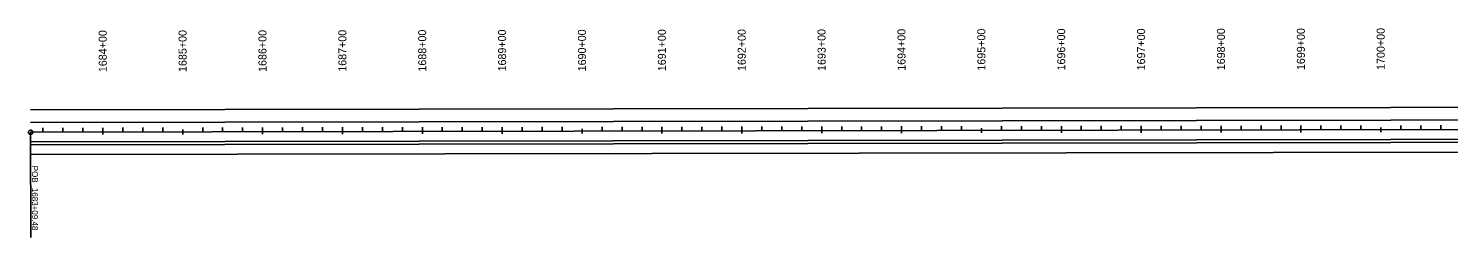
# Model space of a CAD drawing. Extents: x 16513048 to 16518780, y 7009856 to 7010869.
# Drawn here: x 16513048 to 16514826, y 7010221 to 7010483 of the extents above; entities that cross this region are included whole.
import ezdxf

# ---------------------------------------------------------------- set-up
doc = ezdxf.new("R2010")
doc.units = 0
for name, color, linetype in [('dsnNonPlotable', 7, 'Continuous'), ('Level 2', 7, 'Continuous'), ('SheetBorder', 7, 'Continuous'), ('tdCoTitleBlock', 7, 'Continuous')]:
    doc.layers.add(name, color=color, linetype=linetype)

msp = doc.modelspace()

# ---------------------------------------------------------------- linework, layer by layer
at = {"layer": 'dsnNonPlotable'}
for p, q in [((16513050.3, 7010352.9), (16516699.6, 7010359.3)), ((16513050.3, 7010324.9), (16515740.9, 7010329.6))]:
    msp.add_line(p, q, dxfattribs=at)
for points in [[(16513050.2, 7010380.9), (16516699.6, 7010387.3), (16518770.7, 7010388.9)], [(16518770.7, 7010372.9), (16516699.6, 7010371.3), (16513050.3, 7010364.9)], [(16518770.7, 7010348.9), (16516699.6, 7010347.3), (16513050.3, 7010340.9)], [(16518770.7, 7010344.9), (16516699.6, 7010343.3), (16513050.3, 7010336.9)]]:
    msp.add_lwpolyline(points, dxfattribs=at)
at = {"layer": 'Level 2'}
for p in [(16513050.3, 7010352.9), (16513050.5, 7010220.9)]:
    msp.add_line(p, (16513050.5, 7010220.9), dxfattribs=at)
msp.add_circle((16513050.3, 7010352.9), 2.67, dxfattribs=at)
at = {"layer": 'SheetBorder'}
for p, q in [((16513065.8, 7010352.9), (16513065.8, 7010358.4)), ((16513090.8, 7010353), (16513090.8, 7010358.4)), ((16513115.8, 7010353), (16513115.8, 7010358.5)), ((16513140.8, 7010356.1), (16513140.8, 7010350)), ((16513165.8, 7010353.1), (16513165.8, 7010358.6)), ((16513190.8, 7010353.2), (16513190.8, 7010358.6)), ((16513215.8, 7010353.2), (16513215.8, 7010358.7)), ((16513240.8, 7010356.3), (16513240.8, 7010350.2)), ((16513265.8, 7010353.3), (16513265.8, 7010358.7)), ((16513290.8, 7010353.3), (16513290.8, 7010358.8)), ((16513315.8, 7010353.4), (16513315.8, 7010358.8)), ((16513340.8, 7010356.5), (16513340.8, 7010350.4)), ((16513365.8, 7010353.5), (16513365.8, 7010358.9)), ((16513390.8, 7010353.5), (16513390.8, 7010359)), ((16513415.8, 7010353.5), (16513415.8, 7010359)), ((16513440.8, 7010356.7), (16513440.8, 7010350.5)), ((16513465.8, 7010353.6), (16513465.8, 7010359.1)), ((16513490.8, 7010353.7), (16513490.8, 7010359.1)), ((16513515.8, 7010353.7), (16513515.8, 7010359.2)), ((16513540.8, 7010356.8), (16513540.8, 7010350.7)), ((16513565.8, 7010353.8), (16513565.8, 7010359.3)), ((16513590.8, 7010353.9), (16513590.8, 7010359.3)), ((16513615.8, 7010353.9), (16513615.8, 7010359.4)), ((16513640.8, 7010357), (16513640.8, 7010350.9)), ((16513665.8, 7010354), (16513665.8, 7010359.4)), ((16513690.8, 7010354), (16513690.8, 7010359.5)), ((16513715.8, 7010354.1), (16513715.8, 7010359.5)), ((16513740.8, 7010357.2), (16513740.8, 7010351.1)), ((16513765.8, 7010354.2), (16513765.8, 7010359.6)), ((16513790.8, 7010354.2), (16513790.8, 7010359.7)), ((16513815.8, 7010354.2), (16513815.8, 7010359.7)), ((16513840.8, 7010357.4), (16513840.8, 7010351.2)), ((16513865.8, 7010354.3), (16513865.8, 7010359.8)), ((16513890.8, 7010354.4), (16513890.8, 7010359.8)), ((16513915.8, 7010354.4), (16513915.8, 7010359.9)), ((16513940.8, 7010357.5), (16513940.8, 7010351.4)), ((16513965.8, 7010354.5), (16513965.8, 7010360)), ((16513990.8, 7010354.6), (16513990.8, 7010360)), ((16514015.8, 7010354.6), (16514015.8, 7010360.1)), ((16514040.8, 7010357.7), (16514040.8, 7010351.6)), ((16514065.8, 7010354.7), (16514065.8, 7010360.1)), ((16514090.8, 7010354.7), (16514090.8, 7010360.2)), ((16514115.8, 7010354.8), (16514115.8, 7010360.2)), ((16514140.8, 7010357.9), (16514140.8, 7010351.8)), ((16514165.8, 7010354.9), (16514165.8, 7010360.3)), ((16514190.8, 7010354.9), (16514190.8, 7010360.4)), ((16514215.8, 7010354.9), (16514215.8, 7010360.4)), ((16514240.8, 7010358), (16514240.8, 7010351.9)), ((16514265.8, 7010355), (16514265.8, 7010360.5)), ((16514290.8, 7010355.1), (16514290.8, 7010360.5)), ((16514315.8, 7010355.1), (16514315.8, 7010360.6)), ((16514340.8, 7010358.2), (16514340.8, 7010352.1)), ((16514365.8, 7010355.2), (16514365.8, 7010360.7)), ((16514390.8, 7010355.2), (16514390.8, 7010360.7)), ((16514415.8, 7010355.3), (16514415.8, 7010360.8)), ((16514440.8, 7010358.4), (16514440.8, 7010352.3)), ((16514465.8, 7010355.4), (16514465.8, 7010360.8)), ((16514490.8, 7010355.4), (16514490.8, 7010360.9)), ((16514515.8, 7010355.5), (16514515.8, 7010360.9)), ((16514540.8, 7010358.6), (16514540.8, 7010352.5)), ((16514565.8, 7010355.6), (16514565.8, 7010361)), ((16514590.8, 7010355.6), (16514590.8, 7010361.1)), ((16514615.8, 7010355.6), (16514615.8, 7010361.1)), ((16514640.8, 7010358.7), (16514640.8, 7010352.6)), ((16514665.8, 7010355.7), (16514665.8, 7010361.2)), ((16514690.8, 7010355.8), (16514690.8, 7010361.2)), ((16514715.8, 7010355.8), (16514715.8, 7010361.3)), ((16514740.8, 7010358.9), (16514740.8, 7010352.8)), ((16514765.8, 7010355.9), (16514765.8, 7010361.4)), ((16514790.8, 7010355.9), (16514790.8, 7010361.4)), ((16514815.8, 7010356), (16514815.8, 7010361.5))]:
    msp.add_line(p, q, dxfattribs=at)
at = {"layer": 'tdCoTitleBlock'}
for p, q in [((16513140.8, 7010353.1), (16513140.8, 7010358.5)), ((16513240.8, 7010356.3), (16513240.8, 7010350.2)), ((16513340.8, 7010353.4), (16513340.8, 7010358.9)), ((16513440.8, 7010353.6), (16513440.8, 7010359.1)), ((16513540.8, 7010353.8), (16513540.8, 7010359.2)), ((16513640.8, 7010353.9), (16513640.8, 7010359.4)), ((16513740.8, 7010357.2), (16513740.8, 7010351.1)), ((16513840.8, 7010354.3), (16513840.8, 7010359.8)), ((16513940.8, 7010354.5), (16513940.8, 7010359.9)), ((16514040.8, 7010354.6), (16514040.8, 7010360.1)), ((16514140.8, 7010354.8), (16514140.8, 7010360.3)), ((16514240.8, 7010358), (16514240.8, 7010351.9)), ((16514340.8, 7010355.2), (16514340.8, 7010360.6)), ((16514440.8, 7010355.3), (16514440.8, 7010360.8)), ((16514540.8, 7010355.5), (16514540.8, 7010361)), ((16514640.8, 7010355.7), (16514640.8, 7010361.1)), ((16514740.8, 7010358.9), (16514740.8, 7010352.8))]:
    msp.add_line(p, q, dxfattribs=at)

# ---------------------------------------------------------------- texts
at = {"layer": 'Level 2'}
for s, p in [('POB ', (16513052, 7010310.9)), ('1683+09.48', (16513052, 7010283.2))]:
    msp.add_text(s, height=7.5, rotation=270.0999, dxfattribs=at).set_placement(p)
at = {"layer": 'SheetBorder'}
for s, p in [('1684+00', (16513145.7, 7010428.1)), ('1685+00', (16513245.7, 7010428.3)), ('1686+00', (16513345.7, 7010428.4)), ('1687+00', (16513445.7, 7010428.6)), ('1688+00', (16513545.7, 7010428.8)), ('1689+00', (16513645.7, 7010429)), ('1690+00', (16513745.7, 7010429.1)), ('1691+00', (16513845.7, 7010429.3)), ('1692+00', (16513945.7, 7010429.5)), ('1693+00', (16514045.7, 7010429.6)), ('1694+00', (16514145.7, 7010429.8)), ('1695+00', (16514245.7, 7010430)), ('1696+00', (16514345.7, 7010430.2)), ('1697+00', (16514445.7, 7010430.3)), ('1698+00', (16514545.7, 7010430.5)), ('1699+00', (16514645.7, 7010430.7)), ('1700+00', (16514745.7, 7010430.9))]:
    msp.add_text(s, height=10.02, rotation=90.0999, dxfattribs=at).set_placement(p)
at = {"layer": 'tdCoTitleBlock'}
for s, p in [('1685+00', (16513245.7, 7010428.3)), ('1690+00', (16513745.7, 7010429.1)), ('1695+00', (16514245.7, 7010430)), ('1700+00', (16514745.7, 7010430.9))]:
    msp.add_text(s, height=10.02, rotation=90.0999, dxfattribs=at).set_placement(p)

doc.saveas('drawing.dxf')
